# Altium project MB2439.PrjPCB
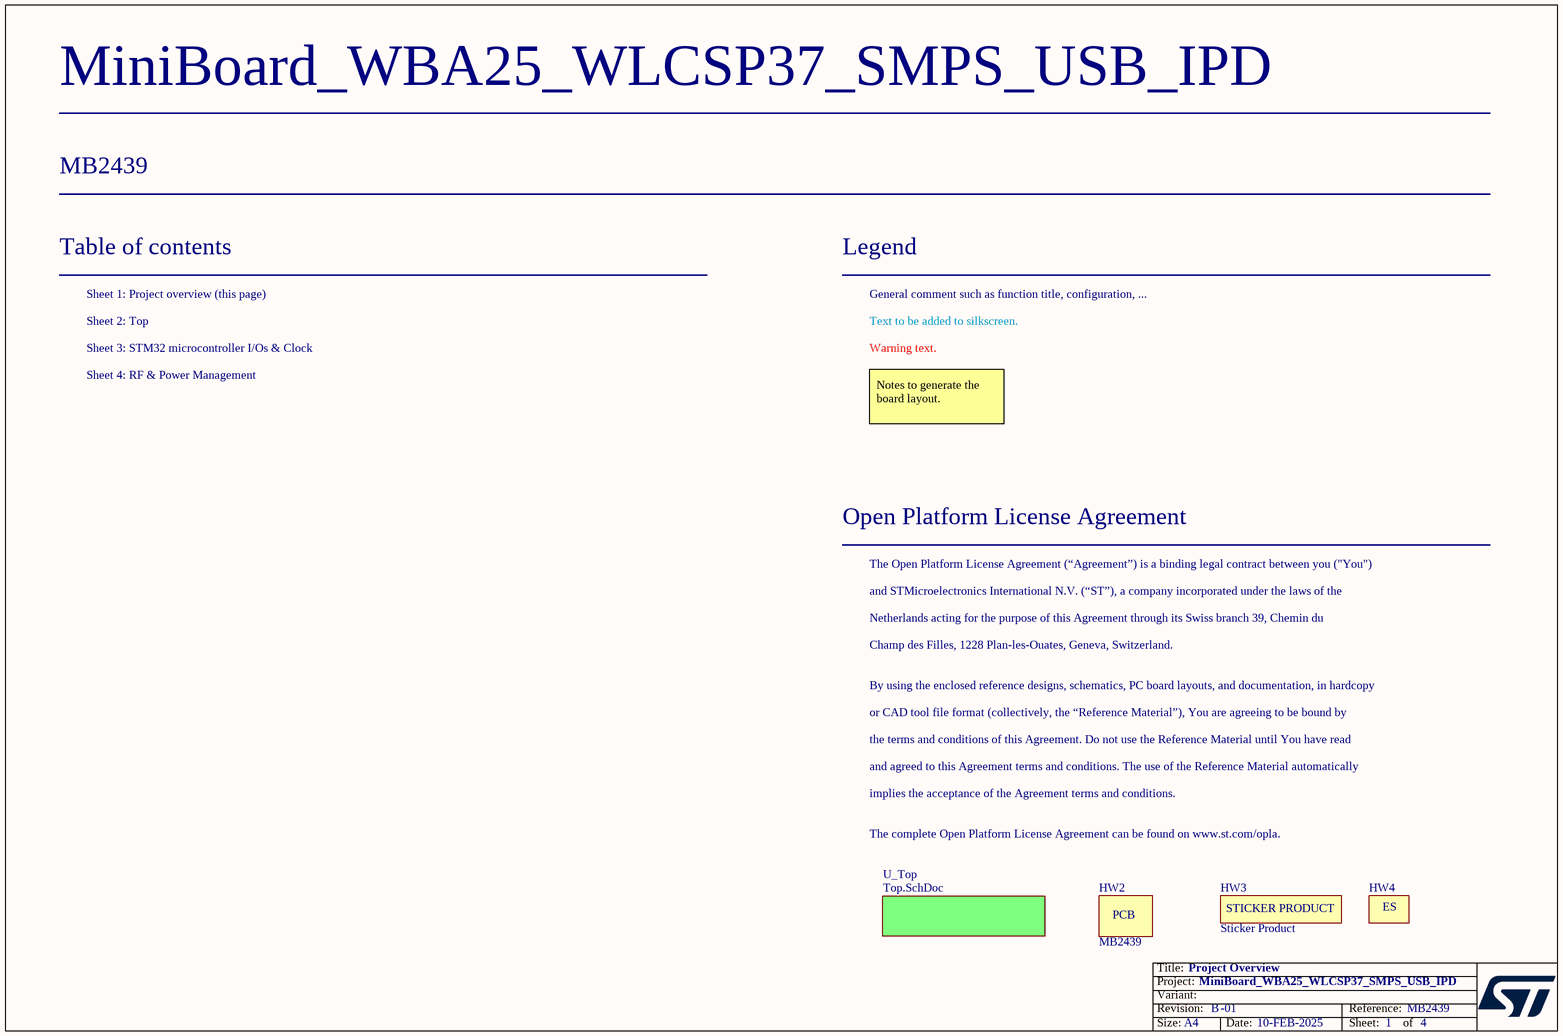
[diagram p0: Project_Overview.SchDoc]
Board_Reference: MB2439; Board_PCB_Revision: B; Board_Name: MiniBoard_WBA25_WLCSP37_SMPS_USB_IPD; Board_Document_Date: 10-FEB-2025; Board_Assembly_Revision: 01
4 sheets, 80 parts. Net scope: flat (ports and power ports of the same name join across sheets).
Board file: MB2439.PcbDoc
Sheets:
  Project_Overview.SchDoc
    U_Top = Top.SchDoc
      STM32 microcontroller I/Os & Clock = MCU.SchDoc
      RF & Power Management Schematic = RF&Power_Management.SchDoc

## Sheet Project_Overview.SchDoc: Project Overview
size A4; Date: Not used; ApprovedBy: Not used; CheckedBy: Not used; Author: Not used; CompanyName: STMicroelectronics; DrawnBy: Not used; Engineer: Not used; Organization: Not used; Address1: Not used; Address2: Not used; Address3: Not used; Address4: Not used; DocumentNumber: Not used; Revision: Not used; SheetNumber: 1; SheetTotal: 4

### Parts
HW2  value MB2439  (hidden comment: PCB)  (mechanical)
HW3  value Sticker Product  [STICKER_PRODUCT_25X9]  (hidden comment: STICKER_PRODUCT)  (no BOM)
HW4  STICKER_ES  [STICKER_ES_6X6]  (value not drawn)  (no BOM)

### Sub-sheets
U_Top = Top.SchDoc: no entries

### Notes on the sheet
- Table of contents
- Sheet 1: Project overview (this page)
- Legend
- General comment such as function title, configuration, ...
- Sheet 2: Top
- Sheet 3: STM32 microcontroller I/Os & Clock
- Sheet 4: RF & Power Management
- Text to be added to silkscreen.
- Warning text.
- Notes to generate the board layout.
- Open Platform License Agreement
- The Open Platform License Agreement (“Agreement”) is a binding legal contract between you ("You")
- and STMicroelectronics International N.V. (“ST”), a company incorporated under the laws of the
- Netherlands acting for the purpose of this Agreement through its Swiss branch 39, Chemin du
- Champ des Filles, 1228 Plan-les-Ouates, Geneva, Switzerland.
- By using the enclosed reference designs, schematics, PC board layouts, and documentation, in hardcopy
- or CAD tool file format (collectively, the “Reference Material”), You are agreeing to be bound by
- the terms and conditions of this Agreement. Do not use the Reference Material until You have read
- and agreed to this Agreement terms and conditions. The use of the Reference Material automatically
- implies the acceptance of the Agreement terms and conditions.
- The complete Open Platform License Agreement can be found on www.st.com/opla.

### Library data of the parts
HW2 = MCD-04980: PCB, MB2439, 47x43mm, 4L2S, 1.6mm, standard, FR4; Part_Preference: Recommended; Manufacturer: PLOTEC; ShowFields: YES; ID: 7096
HW3 = MCD-00547: Sticker product, 25x9mm; Part_Type: Misc; Part_Preference: Recommended; Component_Country_Of_Origin: Unknown; ShowFields: YES; ID: 3197
HW4 = MCD-00234: Sticker ES, 6x6mm; Part_Type: Misc; Part_Preference: Recommended; Component_Country_Of_Origin: Unknown; ShowFields: YES; ID: 2634

## Sheet Top.SchDoc: Top Schematic
size A4; Date: Not used; ApprovedBy: Not used; CheckedBy: Not used; Author: Not used; CompanyName: STMicroelectronics; DrawnBy: Not used; Engineer: Not used; Organization: Not used; Address1: Not used; Address2: Not used; Address3: Not used; Address4: Not used; DocumentNumber: Not used; Revision: Not used; SheetNumber: 2; SheetTotal: 4
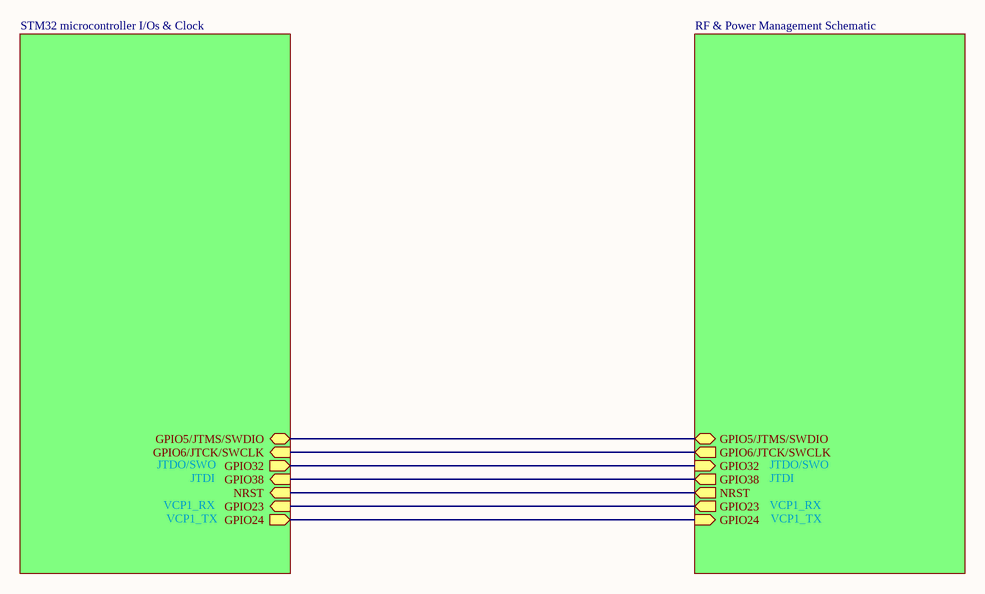
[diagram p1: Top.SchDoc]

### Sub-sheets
RF & Power Management Schematic = RF&Power_Management.SchDoc: GPIO5/JTMS/SWDIO (bidir), GPIO6/JTCK/SWCLK (out), GPIO32 (in), GPIO38 (out), NRST (out), GPIO23 (out), GPIO24 (in)
STM32 microcontroller I/Os & Clock = MCU.SchDoc: GPIO5/JTMS/SWDIO (bidir), GPIO6/JTCK/SWCLK (in), GPIO32 (out), GPIO38 (in), NRST (in), GPIO23 (in), GPIO24 (out)

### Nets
(unnamed): sheet STM32 microcontroller I/Os & Clock/GPIO5/JTMS/SWDIO, sheet RF & Power Management Schematic/GPIO5/JTMS/SWDIO
(unnamed): sheet STM32 microcontroller I/Os & Clock/GPIO6/JTCK/SWCLK, sheet RF & Power Management Schematic/GPIO6/JTCK/SWCLK  [a separate net that carries the same name]
(unnamed): sheet STM32 microcontroller I/Os & Clock/GPIO32, sheet RF & Power Management Schematic/GPIO32  [a separate net that carries the same name]
(unnamed): sheet STM32 microcontroller I/Os & Clock/GPIO38, sheet RF & Power Management Schematic/GPIO38  [a separate net that carries the same name]
(unnamed): sheet STM32 microcontroller I/Os & Clock/NRST, sheet RF & Power Management Schematic/NRST  [a separate net that carries the same name]
(unnamed): sheet STM32 microcontroller I/Os & Clock/GPIO23, sheet RF & Power Management Schematic/GPIO23  [a separate net that carries the same name]
(unnamed): sheet STM32 microcontroller I/Os & Clock/GPIO24, sheet RF & Power Management Schematic/GPIO24  [a separate net that carries the same name]

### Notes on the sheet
- JTDO/SWO
- VCP1_RX
- VCP1_TX
- JTDI

## Sheet MCU.SchDoc: STM32 microcontroller I/Os & Clock
size A4; Date: Not used; ApprovedBy: Not used; CheckedBy: Not used; Author: Not used; CompanyName: STMicroelectronics; DrawnBy: Not used; Engineer: Not used; Organization: Not used; Address1: Not used; Address2: Not used; Address3: Not used; Address4: Not used; DocumentNumber: Not used; Revision: Not used; SheetNumber: 3; SheetTotal: 4
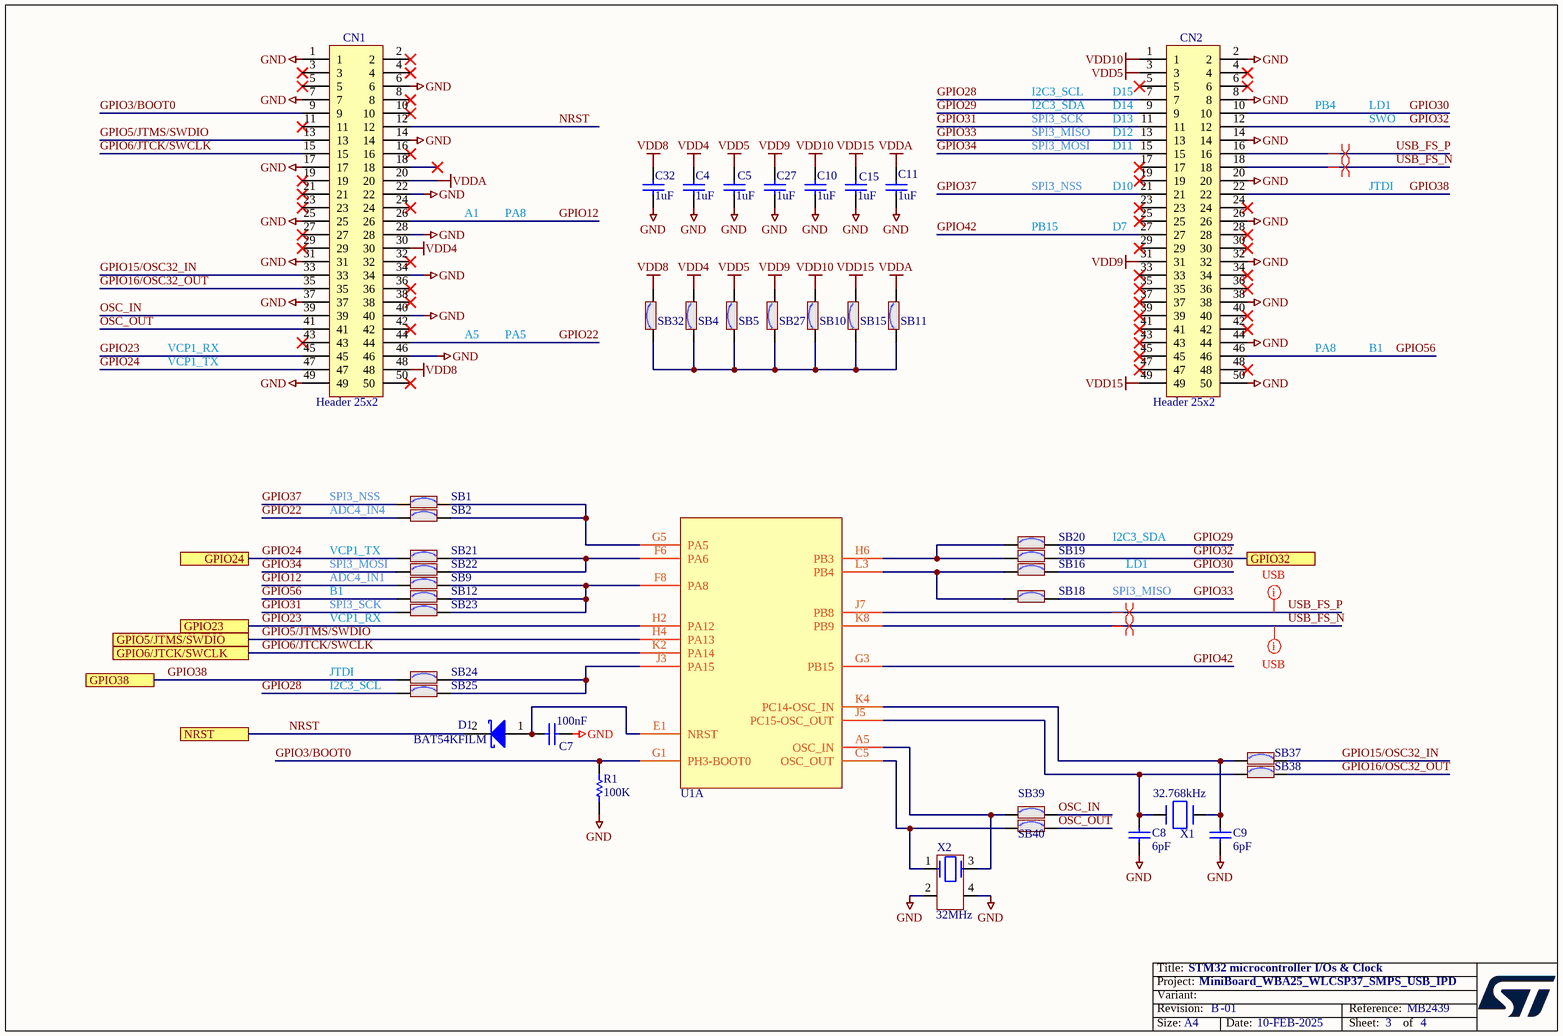
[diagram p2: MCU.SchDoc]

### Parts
C4  value 1uF  [C0402]  (hidden comment: Capacitor)
C5  value 1uF  [C0402]  (hidden comment: Capacitor)
C7  value 100nF  [C0402]  (hidden comment: Capacitor)
C8  value 6pF  [C0402]  (hidden comment: Capacitor)
C9  value 6pF  [C0402]  (hidden comment: Capacitor)
C10  value 1uF  [C0402]  (hidden comment: Capacitor)
C11  value 1uF  [C0402]  (hidden comment: Capacitor)
C15  value 1uF  [C0402]  (hidden comment: Capacitor)
C27  value 1uF  [C0402]  (hidden comment: Capacitor)
C32  value 1uF  [C0402]  (hidden comment: Capacitor)
CN1  Header 25x2  [CON_SAMTEC_FTSH-125-02-L-DV]
CN2  Header 25x2  [CON_SAMTEC_FTSH-125-02-L-DV]
D1  value BAT54KFILM  [DIO_SOD523_1A_2K]  (hidden comment: SCHOTTKY_1A_2K)
R1  value 100K  [R0402]  (hidden comment: Resistor)
SB1  SB_ON  [SOLDER-BRIDGE_R0402-0R]  (value not drawn)
SB2  SB_ON  [SOLDER-BRIDGE_R0402-0R]  (value not drawn)
SB4  SB_ON  [SOLDER-BRIDGE_R0402-0R]  (value not drawn)
SB5  SB_ON  [SOLDER-BRIDGE_R0402-0R]  (value not drawn)
SB9  SB_ON  [SOLDER-BRIDGE_R0402-0R]  (value not drawn)
SB10  SB_ON  [SOLDER-BRIDGE_R0402-0R]  (value not drawn)
SB11  SB_ON  [SOLDER-BRIDGE_R0402-0R]  (value not drawn)
SB12  SB_ON  [SOLDER-BRIDGE_R0402-0R]  (value not drawn)
SB15  SB_ON  [SOLDER-BRIDGE_R0402-0R]  (value not drawn)
SB16  SB_ON  [SOLDER-BRIDGE_R0402-0R]  (value not drawn)
SB18  SB_ON  [SOLDER-BRIDGE_R0402-0R]  (value not drawn)
SB19  SB_ON  [SOLDER-BRIDGE_R0402-0R]  (value not drawn)
SB20  SB_ON  [SOLDER-BRIDGE_R0402-0R]  (value not drawn)
SB21  SB_ON  [SOLDER-BRIDGE_R0402-0R]  (value not drawn)
SB22  SB_ON  [SOLDER-BRIDGE_R0402-0R]  (value not drawn)
SB23  SB_ON  [SOLDER-BRIDGE_R0402-0R]  (value not drawn)
SB24  SB_ON  [SOLDER-BRIDGE_R0402-0R]  (value not drawn)
SB25  SB_ON  [SOLDER-BRIDGE_R0402-0R]  (value not drawn)
SB27  SB_ON  [SOLDER-BRIDGE_R0402-0R]  (value not drawn)
SB32  SB_ON  [SOLDER-BRIDGE_R0402-0R]  (value not drawn)
SB37  SB_ON  [SOLDER-BRIDGE_R0402-0R]  (value not drawn)
SB38  SB_ON  [SOLDER-BRIDGE_R0402-0R]  (value not drawn)
SB39  SB_ON  [SOLDER-BRIDGE_R0402-0R]  (value not drawn)
SB40  SB_ON  [SOLDER-BRIDGE_R0402-0R]  (value not drawn)
U1  STM32WBA25HEF7  [ICC_WLCSP37_2P61X2P41_P035]  (value not drawn)  (part A of 3)
X1  value 32.768kHz  [CRY_NX1610SE_2P]  (hidden comment: XTAL_2_PINS)
X2  value 32MHz  [CRY_NX1612SA_4P]  (hidden comment: XTAL_4_PINS)

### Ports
GPIO5/JTMS/SWDIO, GPIO6/JTCK/SWCLK, GPIO23, GPIO24, GPIO32, GPIO38, NRST

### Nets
GND: C4.1 C5.1 C7.1 C8.1 C9.1 C10.1 C11.1 C15.1 C27.1 C32.1 CN1.1 CN1.6 CN1.7 CN1.14 CN1.17 CN1.22 CN1.25 CN1.28 CN1.31 CN1.34 CN1.37 CN1.40 CN1.46 CN1.49 CN2.2 CN2.8 CN2.14 CN2.20 CN2.26 CN2.32 CN2.38 CN2.44 CN2.50 R1.2 X2.2 X2.4
VDD4: C4.2 CN1.30 SB4.2
VDD5: C5.2 CN2.3 SB5.2
VDD8: C32.2 CN1.48 SB32.2
VDD9: C27.2 CN2.31 SB27.2
VDD10: C10.2 CN2.1 SB10.2
VDD15: C15.2 CN2.49 SB15.2
VDDA: C11.2 CN1.20 SB11.2
GPIO3/BOOT0: CN1.9 R1.1 U1.G1(PH3-BOOT0)
GPIO5/JTMS/SWDIO: CN1.13 U1.H4(PA13) ; port GPIO5/JTMS/SWDIO
GPIO6/JTCK/SWCLK: CN1.15 U1.K2(PA14) ; port GPIO6/JTCK/SWCLK
GPIO12: CN1.26 SB9.1
GPIO15/OSC32_IN: CN1.33 SB37.2
GPIO16/OSC32_OUT: CN1.35 SB38.2
GPIO22: CN1.44 SB2.1
GPIO23: CN1.45 U1.H2(PA12) ; port GPIO23
GPIO24: CN1.47 SB21.1 ; port GPIO24
GPIO28: CN2.7 SB25.1
GPIO29: CN2.9 SB20.2
GPIO30: CN2.10 SB16.2
GPIO31: CN2.11 SB23.1
GPIO32: CN2.12 SB19.2 ; port GPIO32
GPIO33: CN2.13 SB18.2
GPIO34: CN2.15 SB22.1
GPIO37: CN2.21 SB1.1
GPIO38: CN2.22 SB24.1 ; port GPIO38
GPIO42: CN2.27 U1.G3(PB15)
GPIO56: CN2.46 SB12.1
NRST: CN1.12 D1.2(K) ; port NRST
OSC_IN: CN1.39 SB39.2
OSC_OUT: CN1.41 SB40.2
USB_FS_N: CN2.18 U1.K8(PB9)
USB_FS_P: CN2.16 U1.J7(PB8)
NetC7_2: C7.2 D1.1(A) U1.E1(NRST)
NetC8_2: C8.2 SB38.1 U1.J5(PC15-OSC_OUT) X1.2(X2)
NetC9_2: C9.2 SB37.1 U1.K4(PC14-OSC_IN) X1.1(X1)
NetSB1_2: SB1.2 SB2.2 U1.G5(PA5)
NetSB4_1: SB4.1 SB5.1 SB10.1 SB11.1 SB15.1 SB27.1 SB32.1
NetSB9_2: SB9.2 SB12.2 SB23.2 U1.F8(PA8)
NetSB16_1: SB16.1 SB18.1 U1.L3(PB4)
NetSB19_1: SB19.1 SB20.1 U1.H6(PB3)
NetSB21_2: SB21.2 SB22.2 U1.F6(PA6)
NetSB24_2: SB24.2 SB25.2 U1.J3(PA15)
NetSB39_1: SB39.1 U1.A5(OSC_IN) X2.3
NetSB40_1: SB40.1 U1.C5(OSC_OUT) X2.1

Not connected (* = marked no-connect by the designer): CN1 2* 3* 4* 5* 8* 10* 11* 16* 18* 19* 21* 23* 24* 27* 29* 32* 36* 38* 42* 43* 50*; CN2 4* 5* 6* 17* 19* 23* 24* 25* 28* 29* 30* 33* 34* 35* 36* 37* 39* 40* 41* 42* 43* 45* 47* 48*

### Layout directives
rule Matched Net Lengths [Tolerance = 2mm]; rule Impedance Constraint [Min = 80.00    Max = 100.0    ]: USB_FS_N, USB_FS_P
differential pair; differential pair class DIFF90; net class DIFF90: USB_FS_N, USB_FS_P

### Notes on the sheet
- I2C3_SDA
- I2C3_SCL
- (near CN2) D14
- (near CN2) D15
- PB4
- LD1
- SPI3_SCK
- SPI3_MISO
- SPI3_MOSI
- (near CN2) D11
- (near CN2) D13
- (near CN2) D12
- SWO
- A1
- PA8
- PB15
- SPI3_NSS
- (near CN2) D7
- (near CN2) D10
- JTDI
- VCP1_RX
- VCP1_TX
- A5
- PA5
- B1
- ADC4_IN4
- ADC4_IN1

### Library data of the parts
C4 C5 C10 C11 C15 C27 C32 = MCD-01722: Capacitor, MLCC, 1uF, 10V, X5R, +/-10%, 0402, T=0.5mm; Part_Preference: Recommended; Manufacturer: YAGEO; Manufacturer_Part_Number: CC0402KRX5R6BB105; Component_Country_Of_Origin: China; ShowFields: YES; ID: 3822
C7 = MCD-00006: Capacitor, MLCC, 100nF, 16V, X7R, +/-10%, 0402, T=0.5mm; Manufacturer_Part_Number: CC0402KRX7R7BB104; Manufacturer: YAGEO; Part_Preference: Recommended; Partial_Alternate_Internal_Part_Number: MCD-03299; Order_Code_RS: 9402047; Component_Country_Of_Origin: China; ShowFields: YES; ID: 2474
C8 C9 = MCD-03185: Capacitor, MLCC, 6pF, 50V, C0G/NP0, +/-0,25pF, 0402, T=0.5mm; Part_Preference: Recommended; Manufacturer: MURATA; Manufacturer_Part_Number: GJM1555C1H6R0CB01; Order_Code_RS: 170-6040; ShowFields: YES; ID: 5301; Component_Country_Of_Origin: Singapore
CN1 CN2 = MCD-02746: Header, 25x2, 1.27mm, VR, SMD, T=4.83mm; Part_Type: Connector; Part_Preference: Recommended; Manufacturer: SAMTEC; Manufacturer_Part_Number: FTSH-125-02-L-DV; Partial_Alternate_Internal_Part_Number: MCD-03741; ShowFields: YES; ID: 4858; Component_Country_Of_Origin: China, Costa Rica, Malaysia, USA, Vietnam
D1 = MCD-01677: Diode, Schottky, 0V9, 100mA, 40V, SOD-523; Manufacturer: STMICROELECTRONICS; BMS_Part_Number: 9151123; Part_Preference: Recommended; Manufacturer_HQ_COO: EU; Order_Code_RS: 714-6869; Component_Country_Of_Origin: China; ShowFields: YES; ID: 3777
R1 = MCD-00059: Resistor, 100K, 0402, +/-1%, 1/16W; Part_Preference: Recommended; Manufacturer: YAGEO; Manufacturer_Part_Number: RC0402FR-07100KL; Partial_Alternate_Internal_Part_Number: MCD-03301; Order_Code_RS: 2421891; Component_Country_Of_Origin: China; ShowFields: YES; ID: 2533
SB1 SB2 SB4 SB5 SB9-SB12 SB15 SB16 SB18-SB25 SB27 SB32 SB37-SB40 = MCD-01618: Resistor, 0R, SB0402, 5%, 0.063W; Part_Preference: Recommended; Manufacturer: YAGEO; Manufacturer_Part_Number: RC0402JR-070RL; Order_Code_RS: 618-5804; Component_Country_Of_Origin: China; ShowFields: YES; ID: 3718
U1 = MCD-04938: MCU, ARM Cortex-M33 32-bit, 512KB Flash, 96KB RAM, Crypto; Part_Type: IC; Part_Preference: Recommended; Manufacturer: STMICROELECTRONICS; ShowFields: YES; ID: 7054
X1 = MCD-02579: Crystal, 32.768kHz, 6pF, +/-20ppm, 70KR, 1.6x1mm; Part_Type: Crystal_Osc; Part_Preference: Recommended; Manufacturer: NDK; Manufacturer_Part_Number: NX1610SE-32.768KHz-EXS00A-MU01501; ShowFields: YES; ID: 4685; Component_Country_Of_Origin: Japan
X2 = MCD-02578: Crystal, 32MHz, 8pF, +/-10ppm, 40R, 1612(metric); Part_Type: Crystal_Osc; Part_Preference: Recommended; Manufacturer: NDK; Manufacturer_Part_Number: NX1612SA-32MHz-EXS00A-CS09166; ShowFields: YES; ID: 4684; Component_Country_Of_Origin: Japan

## Sheet RF&Power_Management.SchDoc: RF & Power Management Schematic
size A4; Date: Not used; ApprovedBy: Not used; CheckedBy: Not used; Author: Not used; CompanyName: STMicroelectronics; DrawnBy: Not used; Engineer: Not used; Organization: Not used; Address1: Not used; Address2: Not used; Address3: Not used; Address4: Not used; DocumentNumber: Not used; Revision: Not used; SheetNumber: 4; SheetTotal: 4
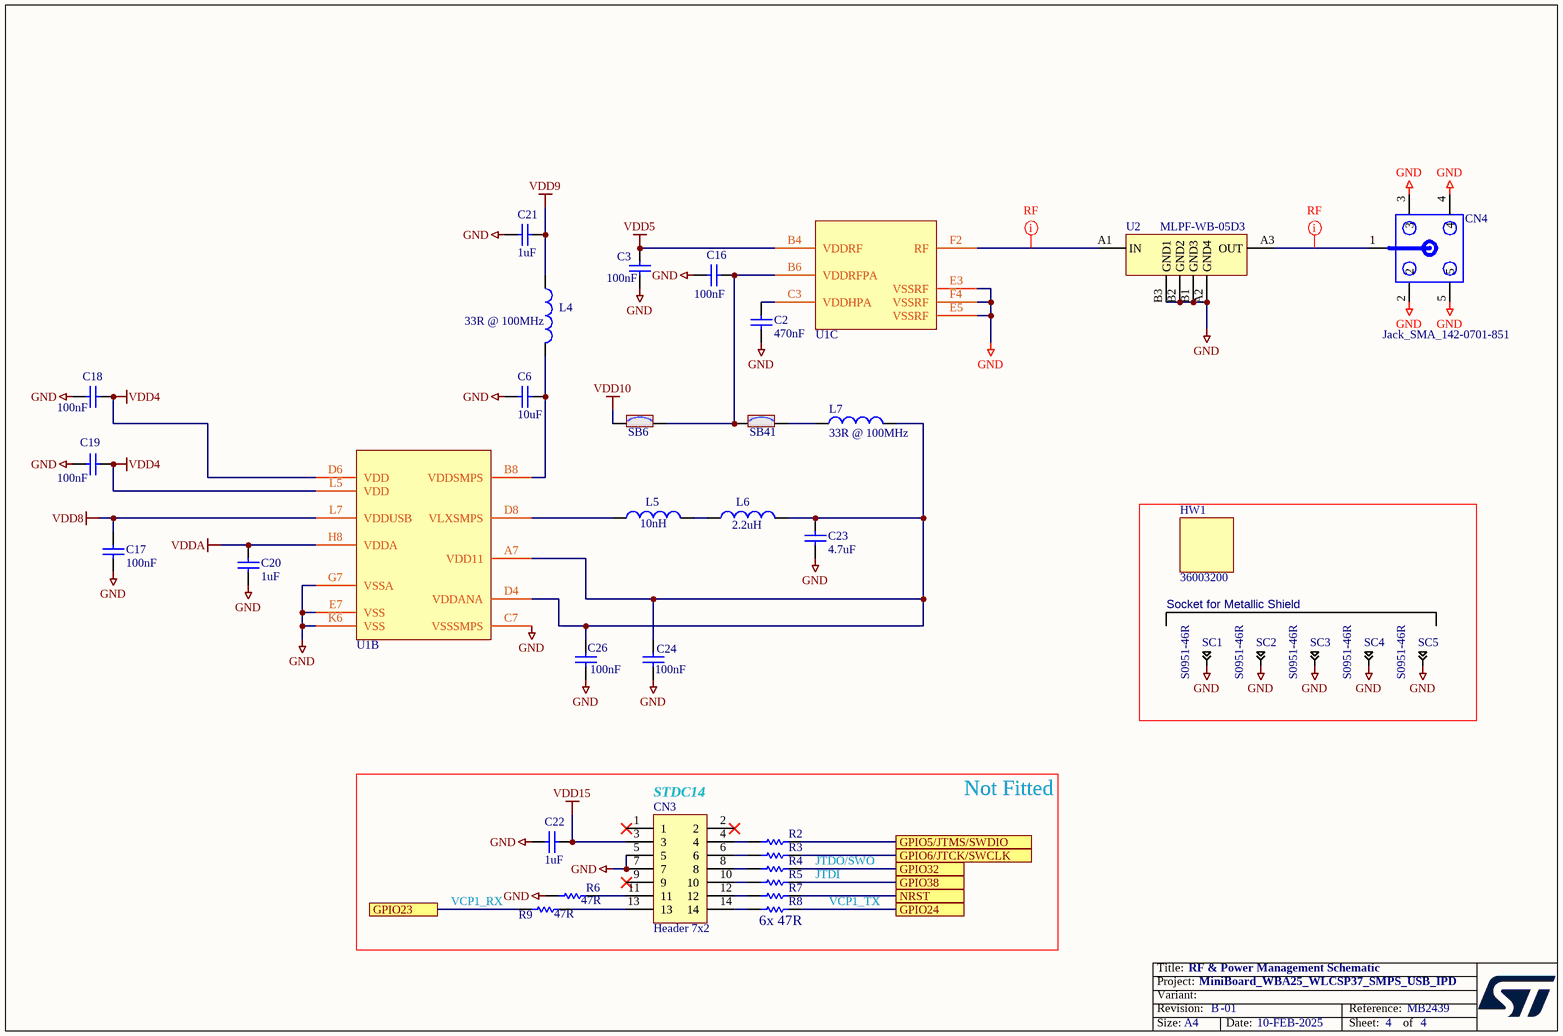
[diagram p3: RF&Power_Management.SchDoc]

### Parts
C2  value 470nF  [C0603_H0P8]  (hidden comment: Capacitor)
C3  value 100nF  [C0402]  (hidden comment: Capacitor)
C6  value 10uF  [C0603_H0P8]  (hidden comment: Capacitor)
C16  value 100nF  [C0402]  (hidden comment: Capacitor)
C17  value 100nF  [C0402]  (hidden comment: Capacitor)
C18  value 100nF  [C0402]  (hidden comment: Capacitor)
C19  value 100nF  [C0402]  (hidden comment: Capacitor)
C20  value 1uF  [C0402]  (hidden comment: Capacitor)
C21  value 1uF  [C0402]  (hidden comment: Capacitor)
C22  value 1uF  [C0402]  (hidden comment: Capacitor)
C23  value 4.7uF  [C0402]  (hidden comment: Capacitor)
C24  value 100nF  [C0402]  (hidden comment: Capacitor)
C26  value 100nF  [C0402]  (hidden comment: Capacitor)
CN3  Header 7x2  [CON_SAMTEC_FTSH-107-01-L-DV-K-A]
CN4  value Jack_SMA_142-0701-851  [CON_SMA-RF_CINCH_142-0701-851]  (hidden comment: SMA-J-P-H-ST-EM1)
HW1  value 36003200  [SHIELD_WURTH_36003200_21P8X21P8]  (hidden comment: Shield Cover)
L4  value 33R @ 100MHz  [C0402]  (hidden comment: BEAD)
L5  value 10nH  [C0402]  (hidden comment: Inductor)
L6  value 2.2uH  [IND_0805_MURATA_LQM21_H1P0]  (hidden comment: Inductor)
L7  value 33R @ 100MHz  [C0402]  (hidden comment: BEAD)
R2  Resistor  [R0402]  (value not drawn)
R3  Resistor  [R0402]  (value not drawn)
R4  Resistor  [R0402]  (value not drawn)
R5  Resistor  [R0402]  (value not drawn)
R6  value 47R  [R0402]  (hidden comment: Resistor)
R7  Resistor  [R0402]  (value not drawn)
R8  Resistor  [R0402]  (value not drawn)
R9  value 47R  [R0402]  (hidden comment: Resistor)
SB6  SB_ON  [SOLDER-BRIDGE_R0402-0R]  (value not drawn)
SB41  SB_ON  [SOLDER-BRIDGE_R0402-0R]  (value not drawn)
SC1  value S0951-46R  [CLIP_HARWIN_S0951-46R]  (hidden comment: Shield-clip_S0951-46R)
SC2  value S0951-46R  [CLIP_HARWIN_S0951-46R]  (hidden comment: Shield-clip_S0951-46R)
SC3  value S0951-46R  [CLIP_HARWIN_S0951-46R]  (hidden comment: Shield-clip_S0951-46R)
SC4  value S0951-46R  [CLIP_HARWIN_S0951-46R]  (hidden comment: Shield-clip_S0951-46R)
SC5  value S0951-46R  [CLIP_HARWIN_S0951-46R]  (hidden comment: Shield-clip_S0951-46R)
U1  STM32WBA25HEF7  [ICC_WLCSP37_2P61X2P41_P035]  (value not drawn)  (parts B,C of 3)
U2  value MLPF-WB-05D3  [ICC_CSPG_6BUMPS_1X1P60_P050-P0577]  (hidden comment: IC_MLPF-WB-05D3)

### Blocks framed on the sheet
Socket for Metallic Shield: HW1 SC1-SC5
Not Fitted: C22 CN3 R2-R9

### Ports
GPIO5/JTMS/SWDIO, GPIO6/JTCK/SWCLK, GPIO23, GPIO24, GPIO32, GPIO38, NRST

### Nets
GND: C2.1 C3.2 C6.2 C16.1 C17.2 C18.2 C19.2 C20.1 C21.2 C22.2 C23.1 C24.2 C26.2 CN3.5 CN3.7 CN4.2 CN4.3 CN4.4 CN4.5 R6.1 SC1.1 SC2.1 SC3.1 SC4.1 SC5.1 U1.C7(VSSSMPS) U1.E3(VSSRF) U1.E5(VSSRF) U1.E7(VSS) U1.F4(VSSRF) U1.G7(VSSA) U1.K6(VSS) U2.A2(GND4) U2.B1(GND3) U2.B2(GND2) U2.B3(GND1)
VDD4: C18.1 C19.1 U1.D6(VDD) U1.L5(VDD)
VDD5: C3.1 U1.B4(VDDRF)
VDD8: C17.1 U1.L7(VDDUSB)
VDD9: C21.1 L4.1
VDD10: SB6.1
VDD15: C22.1 CN3.3
VDDA: C20.2 U1.H8(VDDA)
GPIO5/JTMS/SWDIO: R2.2 ; port GPIO5/JTMS/SWDIO
GPIO6/JTCK/SWCLK: R3.2 ; port GPIO6/JTCK/SWCLK
GPIO23: R9.1 ; port GPIO23
GPIO24: R8.2 ; port GPIO24
GPIO32: R4.2 ; port GPIO32
GPIO38: R5.2 ; port GPIO38
NRST: R7.2 ; port NRST
NetC2_2: C2.2 U1.C3(VDDHPA)
NetC6_1: C6.1 L4.2 U1.B8(VDDSMPS)
NetC16_2: C16.2 SB6.2 SB41.1 U1.B6(VDDRFPA)
NetC23_2: C23.2 C24.1 C26.1 L6.2 L7.2 U1.A7(VDD11) U1.D4(VDDANA)
NetCN3_4: CN3.4 R2.1
NetCN3_6: CN3.6 R3.1
NetCN3_8: CN3.8 R4.1
NetCN3_10: CN3.10 R5.1
NetCN3_11: CN3.11 R6.2
NetCN3_12: CN3.12 R7.1
NetCN3_13: CN3.13 R9.2
NetCN3_14: CN3.14 R8.1
NetCN4_1: CN4.1 U2.A3(OUT)
NetL5_1: L5.1 U1.D8(VLXSMPS)
NetL5_2: L5.2 L6.1
NetL7_1: L7.1 SB41.2
NetU1_F2: U1.F2(RF) U2.A1(IN)

Not connected (* = marked no-connect by the designer): CN3 1* 2* 9*

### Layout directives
net class RF: NetCN4_1, NetU1_F2

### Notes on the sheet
- (near CN3) STDC14
- (near R9) VCP1_RX
- (near R8) 6x 47R
- JTDI
- JTDO/SWO
- VCP1_TX

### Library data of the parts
C2 = MCD-01006: Capacitor, MLCC, 470nF, 16V, X7R, +/-10%, 0603, T=0.8mm; BMS_Part_Number: 9142003; Part_Preference: Recommended; Manufacturer: YAGEO; Manufacturer_Part_Number: CC0603KRX7R7BB474; Order_Code_RS: 200-6576; Component_Country_Of_Origin: China; ShowFields: YES; ID: 3017
C3 C16-C19 C24 C26 = MCD-00006: as C7 on sheet MCU
C6 = MCD-02733: Capacitor, MLCC, 10uF, 10V, X6S, +/-20%, 0603, T=1mm; Part_Preference: Recommended; Manufacturer: MURATA; Manufacturer_Part_Number: GRM188C81A106MA73; Order_Code_RS: 170-6242; Component_Country_Of_Origin: Japan; ShowFields: YES; ID: 4845
C20-C22 = MCD-01722: as C4 on sheet MCU
C23 = MCD-01356: Capacitor, MLCC, 4.7uF, 6V3, X5R, 20%, 0402, T=0.5mm; Part_Preference: Recommended; Manufacturer: MURATA; Manufacturer_Part_Number: GRM155R60J475ME47; Partial_Alternate_Internal_Part_Number: MCD-04455; Order_Code_RS: 814-5230; Component_Country_Of_Origin: Japan°°; ShowFields: YES; ID: 3456
CN3 = MCD-01531: Header, 7x2, 1.27mm, VR, T=5.97mm, FTSH series STDC14 without Alignment Pin; Part_Type: Connector; Part_Preference: Recommended; Manufacturer: SAMTEC; Manufacturer_Part_Number: FTSH-107-01-L-DV-K; Order_Code_RS: 179-9021; Component_Country_Of_Origin: China, Costa Rica, Malaysia, United States, Vietnam
CN4 = MCD-02072: Jack_SMA, VR, PCB edge, 50R, T=7.92mm; Part_Type: Connector; Part_Preference: Recommended; Manufacturer: CINCH; Manufacturer_Part_Number: 142-0701-851; Order_Code_RS: 885-7532; Component_Country_Of_Origin: USA°°; ShowFields: YES; ID: 4172
HW1 = MCD-04686: RF Shield cover, 21.5x21.5x3.3mm; Part_Type: Misc; Part_Preference: Recommended; Manufacturer: WURTH ELEKTRONIK; Order_Code_RS: 773-7282; Component_Country_Of_Origin: Germany°; ShowFields: YES; ID: 6802
L4 L7 = MCD-04372: Ferrite bead, 33R @ 100MHz, 3A, 22mR, 0402, T=0.5mm; Part_Type: Inductor; Part_Preference: Recommended; Manufacturer: MURATA; Manufacturer_Part_Number: BLM15PX330SN1; Component_Country_Of_Origin: Japan, Thailand; ShowFields: YES; ID: 6488
L5 = MCD-03035: Inductor, 10nH, +/-2%, 0.5A, 260mR, 0402, T=0.5mm; Part_Preference: Recommended; Manufacturer: MURATA; Manufacturer_Part_Number: LQG15HS10NJ02D; Order_Code_RS: 124-8162; ShowFields: YES; ID: 5151; Component_Country_Of_Origin: Japan
L6 = MCD-04691: Inductor, 2.2uH, +/-30%, 0.6A, 0R23, 0805, T=0.9mm; Part_Preference: Recommended; Manufacturer: MURATA; Manufacturer_Part_Number: LQM21PN2R2NGC; Order_Code_RS: 167-4839; Component_Country_Of_Origin: Japan; ShowFields: YES; ID: 6807
R2-R9 = MCD-00481: Resistor, 47R, 0402, +/-1%, 1/16W; Manufacturer_Part_Number: RC0402FR-0747RL; Manufacturer: YAGEO; Part_Preference: Recommended; Component_Country_Of_Origin: China; ShowFields: YES; ID: 2796
SB6 SB41 = MCD-01618: as SB1 on sheet MCU
SC1-SC5 = MCD-01587: shield clip Harwin S0951-46R to fix RF shielded cavity; Part_Type: Misc; Part_Preference: Recommended; Component_Country_Of_Origin: South Korea
U1 = MCD-04938: as U1 on sheet MCU
U2 = MCD-05125: IC, 2.4GHz low pass filter matched to WBA CSP package mini board; Part_Preference: Recommended; Manufacturer: STMICROELECTRONICS; Order_Code_RS: 719-629; ShowFields: YES; ID: 7241

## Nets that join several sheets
GND: MCU (36 pins), RF&Power_Management (36 pins)
VDD4: MCU (C4.2 CN1.30 SB4.2), RF&Power_Management (C18.1 C19.1 U1.D6 U1.L5)
VDD5: MCU (C5.2 CN2.3 SB5.2), RF&Power_Management (C3.1 U1.B4)
VDD8: MCU (C32.2 CN1.48 SB32.2), RF&Power_Management (C17.1 U1.L7)
VDD9: MCU (C27.2 CN2.31 SB27.2), RF&Power_Management (C21.1 L4.1)
VDD10: MCU (C10.2 CN2.1 SB10.2), RF&Power_Management (SB6.1)
VDD15: MCU (C15.2 CN2.49 SB15.2), RF&Power_Management (C22.1 CN3.3)
VDDA: MCU (C11.2 CN1.20 SB11.2), RF&Power_Management (C20.2 U1.H8)
GPIO5/JTMS/SWDIO: MCU (CN1.13 U1.H4), RF&Power_Management (R2.2)
GPIO6/JTCK/SWCLK: MCU (CN1.15 U1.K2), RF&Power_Management (R3.2)
GPIO23: MCU (CN1.45 U1.H2), RF&Power_Management (R9.1)
GPIO24: MCU (CN1.47 SB21.1), RF&Power_Management (R8.2)
GPIO32: MCU (CN2.12 SB19.2), RF&Power_Management (R4.2)
GPIO38: MCU (CN2.22 SB24.1), RF&Power_Management (R5.2)
NRST: MCU (CN1.12 D1.2), RF&Power_Management (R7.2)

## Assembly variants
WBA25HE: not fitted C4 C5 C10 C11 C15 C22 C27 C32 CN3 R2 R3 R4 R5 R6 R7 R8 R9 SB1 SB4 SB5 SB6 SB9 SB10 SB11 SB15 SB18 SB20 SB22 SB23 SB25 SB27 SB32 SB37 SB38 SB39 SB40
